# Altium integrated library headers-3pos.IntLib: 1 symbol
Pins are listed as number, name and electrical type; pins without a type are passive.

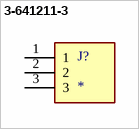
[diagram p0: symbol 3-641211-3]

## 3-641211-3
designator J?
MP: 3-641211-3
footprint TE_3-641211-3
pins: 1, 2, 3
